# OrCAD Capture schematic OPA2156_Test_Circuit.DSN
size A; title: OPA2156 36-V, Ultra-Low Noise, Wide-Bandwidth, CMOS, Precision,; rev: 1.1; note: Datasheet: SBOS900B   EVM: N/A
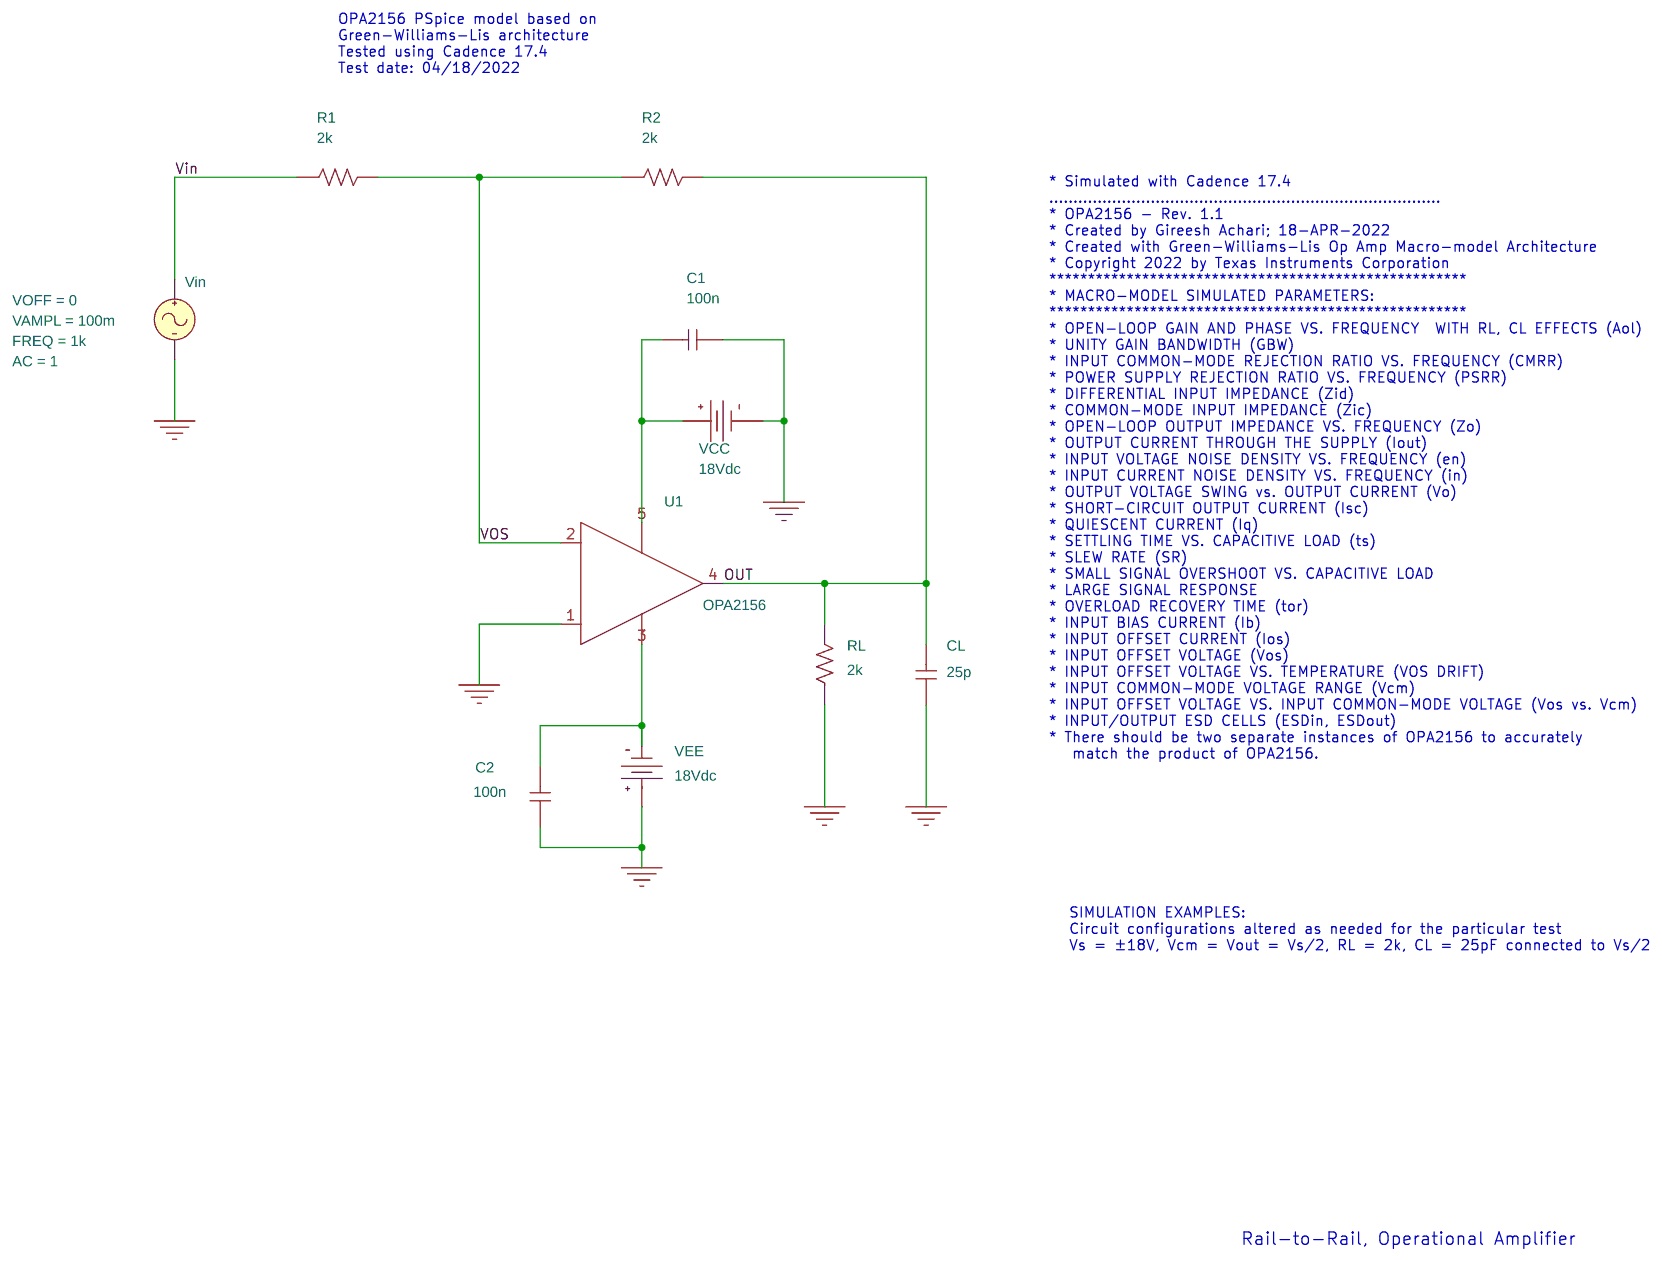
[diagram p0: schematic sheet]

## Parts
C1  100n  [cap196]
C2  100n  [cap196]
CL  25p  [cap196]
R1  2k  [AXRC05]
R2  2k  [AXRC05]
RL  2k  [AXRC05]
U1  OPA2156
VCC  VDC
VEE  VDC
Vin  VSIN

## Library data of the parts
C1 C2 CL = C
R1 R2 RL = R
U1 = OPA2156
VCC VEE = VDC: DC: 18Vdc
Vin = VSIN: AC: 1; FREQ: 1k; VAMPL: 100m; VOFF: 0

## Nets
Vin: R1.1 Vin.1(+)
0: C1.2 C2.1 CL.2 RL.1 U1.1(+) VCC.1(-) VEE.0(+) Vin.2(-)
OUT: CL.1 R2.2 RL.2 U1.4(OUT)
VOS: R1.2 R2.1 U1.2(-)
N27303: C1.1 U1.5(V+) VCC.0(+)
N27354: C2.2 U1.3(V-) VEE.1(-)

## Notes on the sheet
- OPA2156 PSpice model based on
  Green-Williams-Lis architecture
  Tested using Cadence 17.4
  Test date: 04/18/2022
- * Simulated with Cadence 17.4
  .................................................................................
  * OPA2156 - Rev. 1.1
  * Created by Gireesh Achari; 18-APR-2022
  * Created with Green-Williams-Lis Op Amp Macro-model Architecture
  * Copyright 2022 by Texas Instruments Corporation
  ******************************************************
  * MACRO-MODEL SIMULATED PARAMETERS:
  ******************************************************
  * OPEN-LOOP GAIN AND PHASE VS. FREQUENCY  WITH RL, CL EFFECTS (Aol)
  * UNITY GAIN BANDWIDTH (GBW)
  * INPUT COMMON-MODE REJECTION RATIO VS. FREQUENCY (CMRR)
  * POWER SUPPLY REJECTION RATIO VS. FREQUENCY (PSRR)
  * DIFFERENTIAL INPUT IMPEDANCE (Zid)
  * COMMON-MODE INPUT IMPEDANCE (Zic)
  * OPEN-LOOP OUTPUT IMPEDANCE VS. FREQUENCY (Zo)
  * OUTPUT CURRENT THROUGH THE SUPPLY (Iout)
  * INPUT VOLTAGE NOISE DENSITY VS. FREQUENCY (en)
  * INPUT CURRENT NOISE DENSITY VS. FREQUENCY (in)
  * OUTPUT VOLTAGE SWING vs. OUTPUT CURRENT (Vo)
  * SHORT-CIRCUIT OUTPUT CURRENT (Isc)
  * QUIESCENT CURRENT (Iq)
  * SETTLING TIME VS. CAPACITIVE LOAD (ts)
  * SLEW RATE (SR)
  * SMALL SIGNAL OVERSHOOT VS. CAPACITIVE LOAD
  * LARGE SIGNAL RESPONSE
  * OVERLOAD RECOVERY TIME (tor)
  * INPUT BIAS CURRENT (Ib)
  * INPUT OFFSET CURRENT (Ios)
  * INPUT OFFSET VOLTAGE (Vos)
  * INPUT OFFSET VOLTAGE VS. TEMPERATURE (VOS DRIFT)
  * INPUT COMMON-MODE VOLTAGE RANGE (Vcm)
  * INPUT OFFSET VOLTAGE VS. INPUT COMMON-MODE VOLTAGE (Vos vs. Vcm)
  * INPUT/OUTPUT ESD CELLS (ESDin, ESDout)
  * There should be two separate instances of OPA2156 to accurately
     match the product of OPA2156.
- SIMULATION EXAMPLES:
  Circuit configurations altered as needed for the particular test
  Vs = ±18V, Vcm = Vout = Vs/2, RL = 2k, CL = 25pF connected to Vs/2
- Rail-to-Rail, Operational Amplifier
